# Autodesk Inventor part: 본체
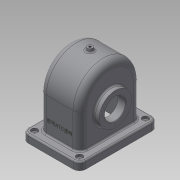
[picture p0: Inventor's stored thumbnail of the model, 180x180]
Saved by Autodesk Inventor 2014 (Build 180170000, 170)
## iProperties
Created: 2016-10
Part Number: 본체
Material: 일반
Document SubType Name: Modeling
Designer: q
Density: 1 g/cm^3
Appearance: 기본값
Mass: 429.775 g
Surface Area: 1201.17 cm^2
Volume: 429.775 cm^3
Author: q
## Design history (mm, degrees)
sketch "스케치1"
  geometry: L1 (-55, 75)-(55, 75); L2 (55, 75)-(55, -75); L3 (55, -75)-(-55, -75); L4 (-55, -75)-(-55, 75); L5 (-55, 75)-(55, -75); L6 (55, 75)-(-55, -75); 3 further points
  constraints: 12 end point, 3 midpoint, 2 parallel, 1 coincident, 1 horizontal, 1 perpendicular
  dimensions: "d0" = 110 distance of L1.start L1.end; "d1" = 150 distance of L3.end L1.start
extrude "돌출1" new body sketch "스케치1" distance "d2" = 15; taper "d3" = 0 deg
fillet "모깎기1" dims "d4" = 12
sketch "스케치2"
  geometry: A1 r 12 centre (-43, 63) between (-43, 75) and (-55, 63) reference; A2 r 12 centre (-43, -63) between (-55, -63) and (-43, -75) reference; A3 r 12 centre (43, -63) between (43, -75) and (55, -63) reference; A4 r 12 centre (43, 63) between (55, 63) and (43, 75) reference; 1 further point
hole "구멍1" sketch "스케치2" at (-43, 63), (-43, -63), (43, -63), (43, 63) diameter "d5" = 5; stored, may be unused: countersink angle "d9" = 90 deg, drill point angle "d11" = 118 deg; dims "d6" = 6, "d7" = 12, "d8" = 5, "d10" = 8
fillet "모깎기2" dims "d12" = 3
sketch "스케치3"
  geometry: L1 (75, 12)-(75, 0) reference; L2 (75, 0)-(-75, 0) reference; L3 (-75, 0)-(-75, 12) reference; L4 (-72, 15)-(72, 15) reference; L5 (-58, 80)-(-58, 15); L6 (58, 80)-(58, 15); A1 r 3 centre (72, 12) between (75, 12) and (72, 15) reference; A2 r 3 centre (-72, 12) between (-72, 15) and (-75, 12) reference; A3 r 58 centre (0, 80) between (58, 80) and (-58, 80); 2 further points
  constraints: 4 end point, 2 point on circle, 2 point on line, 2 tangent, 2 vertical, 1 centre point, 1 midpoint, 1 vertical alignment
  dimensions: "d13" = 80 distance from line of L2 A3.centre; "d14" = 116 diameter of A3
extrude "돌출2" join sketch "스케치3" stored distance "d15" = 77; taper "d16" = 0 deg
sketch "스케치4"
  geometry: L1 (0, 63)-(0, -63) reference; C1 r 31 at (-65, 0); A1 r 58 centre (-80, 0) between (-80, 58) and (-80, -58) reference; 1 further point
  constraints: 1 centre point, 1 horizontal alignment
  dimensions: "d17" = 62 diameter of C1; "d18" = 65 distance from line of L1 C1.centre
extrude "돌출3" join sketch "스케치4" distance "d19" = 10; taper "d20" = 0 deg
sketch "스케치5"
  geometry: C1 r 31 at (0, 0) reference; 5 further points
  constraints: 1 vertical alignment, 5 other
  dimensions: "d21" = 26 distance of C1.centre point (0, -26); "d24" = 360 deg dimension on C1.centre point (0, -26) (derived)
hole "구멍2" sketch "스케치5" at (0, -26), (26, 0), (0, 26), (-26, 0) diameter "d26" = 2.459; stored, may be unused: countersink angle "d30" = 90 deg, drill point angle "d32" = 118 deg; dims "d27" = 6, "d28" = 12, "d29" = 5, "d31" = 8
sketch "스케치6"
  geometry: C1 r 37.5 at (65, 0); C2 r 31 at (65, 0) reference; 1 further point
  constraints: 1 centre point, 1 coincident
  dimensions: "d33" = 75 diameter of C1
extrude "돌출4" join sketch "스케치6" distance "d34" = 5; taper "d35" = 0 deg
sketch "스케치7"
  geometry: C1 r 37.5 at (0, 0) reference; 5 further points
  constraints: 1 vertical alignment, 5 other
  dimensions: "d36" = 29 distance of C1.centre point (0, 29); "d39" = 360 deg dimension on C1.centre point (0, 29) (derived)
hole "구멍3" sketch "스케치7" at (0, 29), (-29, 0), (0, -29), (29, 0) diameter "d41" = 2.459; stored, may be unused: countersink angle "d45" = 90 deg, drill point angle "d47" = 118 deg; dims "d42" = 6, "d43" = 12, "d44" = 5, "d46" = 8
sketch "스케치8"
  geometry: L1 (75, 12)-(75, 0) reference; L2 (75, 0)-(-75, 0) reference; L3 (-75, 0)-(-75, 12) reference; L4 (-72, 15)-(-58, 15) reference; L5 (-58, 15)-(-58, 80) reference; L6 (58, 80)-(58, 15) reference; L7 (58, 15)-(72, 15) reference; L8 (-52, 80)-(-52, 0); L9 (52, 0)-(52, 80); A1 r 3 centre (72, 12) between (75, 12) and (72, 15) reference; A2 r 3 centre (-72, 12) between (-72, 15) and (-75, 12) reference; A3 r 58 centre (0, 80) between (58, 80) and (-58, 80) reference; A4 r 52 centre (0, 80) between (52, 80) and (-52, 80)
  constraints: 4 end point, 2 point on circle, 2 point on line, 1 centre point
  dimensions: "d48" = 6 radial gap between concentric circles of A4 A3; "d49" = 6 distance between parallel lines of L5 L8; "d51" = 6 distance between parallel lines of L6 L9
extrude "돌출5" cut sketch "스케치8" stored distance "d52" = 67; taper "d53" = 0 deg
sketch "스케치9"
  geometry: C1 r 31 at (0, 0) reference; 1 further point
hole "구멍4" sketch "스케치9" at (0, 0) diameter "d54" = 40; stored, may be unused: countersink angle "d58" = 90 deg, drill point angle "d60" = 118 deg; dims "d55" = 6, "d56" = 12, "d57" = 5, "d59" = 8
sketch "스케치10"
  geometry: L1 (-48.5, 96)-(-38.5, 96) reference; L2 (-38.5, 96)-(-38.5, 138) reference; L3 (-38.5, 138)-(38.5, 138) reference; L4 (38.5, 138)-(38.5, 102.5) reference; L5 (38.5, 102.5)-(43.5, 102.5) reference; L6 (43.5, 102.5)-(43.5, 95.23) reference; L7 (43.5, 95.23)-(35.5, 95.23) reference; L8 (35.5, 95.23)-(34.761, 94) reference; L9 (34.761, 94)-(35.5, 92.771) reference; L10 (35.5, 92.771)-(43.5, 92.771) reference; L11 (43.5, 92.771)-(43.5, 85) reference; L12 (43.5, 85)-(33.5, 85) reference; L13 (33.5, 85)-(33.5, 132) reference; L14 (33.5, 132)-(-33.5, 132) reference; L15 (-33.5, 132)-(-33.5, 85) reference; L16 (-33.5, 85)-(-48.5, 85) reference; L17 (-48.5, 85)-(-48.5, 89.77) reference; L18 (-48.5, 89.77)-(-40.5, 89.77) reference; L19 (-40.5, 89.77)-(-39.761, 91) reference; L20 (-39.761, 91)-(-40.5, 92.229) reference; L21 (-40.5, 92.229)-(-48.5, 92.229) reference; L22 (-48.5, 92.229)-(-48.5, 96) reference; L23 (-52, 15)-(-38.5, 15) reference; L24 (-38.5, 15)-(-38.5, 34) reference; L25 (-38.5, 34)-(-48.5, 34) reference; L26 (-48.5, 34)-(-48.5, 37.77) reference; L27 (-48.5, 37.77)-(-40.5, 37.77) reference; L28 (-40.5, 37.77)-(-39.761, 39) reference; L29 (-39.761, 39)-(-40.5, 40.23) reference; L30 (-40.5, 40.23)-(-48.5, 40.23) reference; L31 (-48.5, 40.23)-(-48.5, 45) reference; L32 (-48.5, 45)-(-33.5, 45) reference; L33 (-33.5, 45)-(-33.5, 0) reference; L34 (-33.5, 0)-(-55, 0) reference; L35 (-55, 0)-(-55, 12) reference; L36 (55, 12)-(55, 0) reference; L37 (55, 0)-(33.5, 0) reference; L38 (33.5, 0)-(33.5, 45) reference; L39 (33.5, 45)-(43.5, 45) reference; L40 (43.5, 45)-(43.5, 37.229) reference; L41 (43.5, 37.229)-(35.5, 37.229) reference; L42 (35.5, 37.229)-(34.761, 36) reference; L43 (34.761, 36)-(35.5, 34.77) reference; L44 (35.5, 34.77)-(43.5, 34.77) reference; L45 (43.5, 34.77)-(43.5, 27.5) reference; L46 (43.5, 27.5)-(38.5, 27.5) reference; L47 (38.5, 27.5)-(38.5, 15) reference; L48 (38.5, 15)-(52, 15) reference; L49 (33.5, 104.747)-(19.5, 93); L50 (19.5, 93)-(19.5, 65); L51 (33.5, 65)-(19.5, 65); L52 (-33.5, 0)-(33.5, 0) reference; L53 (33.5, 45)-(33.5, 85) reference; A1 r 3 centre (-52, 12) between (-52, 15) and (-55, 12) reference; A2 r 3 centre (52, 12) between (55, 12) and (52, 15) reference; 1 further point
  constraints: 6 end point, 1 horizontal, 1 midpoint, 1 point on line, 1 vertical
  dimensions: "d61" = 65 distance between parallel lines of L52 L51; "d62" = 28 distance of L49.end L50.end; "d63" = 50 deg angle of L50 L49; "d64" = 14 distance of L51.start L50.end
revolve "회전1" sketch "스케치10" stored, may be unused: angle "d65" = 90 deg
sketch "스케치11"
  geometry: C1 r 20 at (0, 0) reference; 1 further point
hole "구멍5" sketch "스케치11" at (0, 0) diameter "d66" = 40; stored, may be unused: countersink angle "d70" = 90 deg, drill point angle "d72" = 118 deg; dims "d67" = 6, "d68" = 12, "d69" = 5, "d71" = 8
node "작업 평면1"
sketch "스케치12"
  geometry: C1 r 6 at (0, 0); 1 further point
  constraints: 1 centre point, 1 coincident
  dimensions: "d74" = 12 diameter of C1
extrude "돌출6" join sketch "스케치12" distance "d75" = 7; taper "d76" = 0 deg
sketch "스케치13"
  geometry: C1 r 6 at (0, 0) reference
hole "구멍6" sketch "스케치13" at (0, 0) diameter "d77" = 4.459; stored, may be unused: countersink angle "d81" = 90 deg, drill point angle "d83" = 118 deg; dims "d78" = 6, "d79" = 12, "d80" = 5, "d82" = 8
feature "면 기울기1" dims angle "d84" = 10 deg
fillet "모깎기3" dims "d85" = 3
fillet "모깎기4" dims "d86" = 3
fillet "모깎기5" dims "d87" = 13
fillet "모깎기6" dims "d88" = 3
fillet "모깎기7" dims "d89" = 8
node "작업 평면2"
sketch "스케치14"
  geometry: L1 (68.5, -80)-(-17.5, -80) reference; L2 (-13, 0)-(-13, -62) reference; 2 further points
  constraints: 1 other
  dimensions: "d91" = 40 distance from line of L1 point (25.5, -40); "d92" = 38.5 distance from line of point (25.5, -40) L2
feature "엠보싱1" sketch "스케치14" dims "d0" = 110, "d1" = 150, "d93" = 0.5, "d94" = 0
chamfer "모따기1" distance "d95" = 1; stored, may be unused: second distance "d96" = 2, angle "d97" = 45 deg
fillet "모깎기8" dims "d98" = 3
node "솔리드1"
node "절단 모서리 투영1"
node "절단 모서리 투영2"
node "절단 모서리 투영3"
other parameters: "d73" = -144, "d90" = 44.25
